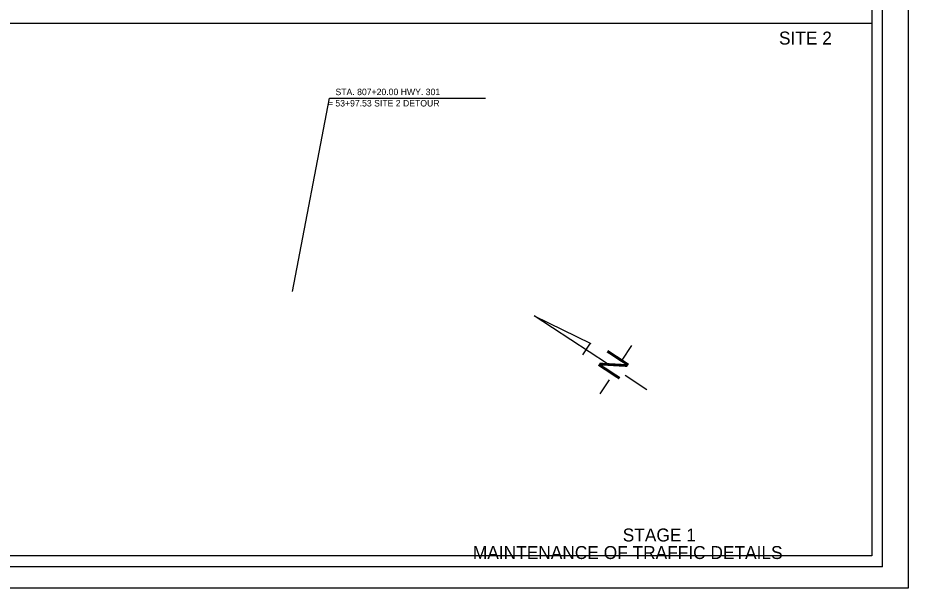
# Model space of a CAD drawing. Extents: x 1368648 to 1927880, y -1037443 to 380209.
# Drawn here: x 1374595 to 1375421, y 378686 to 379215 of the extents above; entities that cross this region are included whole.
import ezdxf

# ---------------------------------------------------------------- set-up
doc = ezdxf.new("R2010")
doc.units = 0
for name, color, linetype in [('R_Border', 7, 'Continuous'), ('R_Border Title', 7, 'Continuous'), ('R_Detour Annot Limits', 7, 'Continuous'), ('R_Draft', 7, 'Continuous'), ('R_No Plot', 7, 'Continuous')]:
    doc.layers.add(name, color=color, linetype=linetype)

msp = doc.modelspace()

# ---------------------------------------------------------------- linework, layer by layer
at = {"layer": 'R_Border'}
for q in [(1375396.77, 379733.26), (1373815.87, 378705.96)]:
    msp.add_line((1375396.77, 378705.96), q, dxfattribs=at)
at = {"layer": 'R_Detour Annot Limits'}
for p, q in [((1374849.77, 378960.98), (1374884.2, 379140.21)), ((1374884.2, 379140.21), (1375028.57, 379140.21))]:
    msp.add_line(p, q, dxfattribs=at)
at = {"layer": 'R_Draft'}
for p, q in [((1375073.74, 378938.57), (1375126.37, 378912.7)), ((1375141.73, 378893.89), (1375073.74, 378938.57)), ((1375118.91, 378902.14), (1375126.01, 378912.95)), ((1375155.38, 378897.21), (1375164.44, 378910.99)), ((1375178.2, 378869.93), (1375158.21, 378883.06)), ((1375135.05, 378866.27), (1375143.52, 378879.16))]:
    msp.add_line(p, q, dxfattribs=at)
at = {"layer": 'R_No Plot'}
for points in [[(1373753.84, 379752.73), (1375420.54, 379752.73), (1375420.54, 378686.04), (1373753.84, 378686.04)], [(1373825.87, 379723.26), (1375073.57, 379723.26), (1375073.57, 379673.86), (1375161.27, 379673.86), (1375281.77, 379673.86), (1375281.77, 379562.19), (1375386.77, 379562.19), (1375386.77, 378715.96), (1373825.87, 378715.96)], [(1373825.87, 379209.61), (1375386.77, 379209.61), (1375386.77, 378715.96), (1373825.87, 378715.96)], [(1373825.87, 379209.61), (1375386.77, 379209.61), (1375386.77, 378715.96), (1373825.87, 378715.96)]]:
    msp.add_lwpolyline(points, close=True, dxfattribs=at)

# ---------------------------------------------------------------- texts
at = {"layer": 'R_Border Title'}
for s, p in [('SITE 2', (1375300.76, 379189.84)), ('STAGE 1', (1375155.92, 378729.32)), ('MAINTENANCE OF TRAFFIC DETAILS', (1375017.02, 378713.07))]:
    msp.add_text(s, height=12, dxfattribs=at).set_placement(p)
at = {"layer": 'R_Detour Annot Limits'}
for s, p in [('STA. 807+20.00 HWY. 301', (1374889.64, 379142.94)), ('= 53+97.53 SITE 2 DETOUR', (1374882.63, 379132.44))]:
    msp.add_text(s, height=6, rotation=360, dxfattribs=at).set_placement(p)
at = {"layer": 'R_Draft'}
msp.add_text('N', height=23.27, rotation=56.6872, dxfattribs=at).set_placement((1375150.89, 378877.32))

doc.saveas('drawing.dxf')
